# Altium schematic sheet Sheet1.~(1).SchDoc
size A4
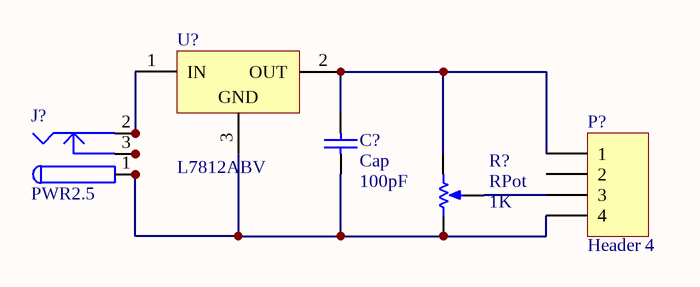
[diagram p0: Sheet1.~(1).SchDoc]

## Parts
C?  Cap  value 100pF  [RAD-0.3]
J?  PWR2.5  [KLD-0202]
P?  Header 4  [HDR1X4]
R?  RPot  value 1K  [VR5]
U?  L7812ABV  [TO220ABN]

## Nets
NetC?_1: C?.1 J?.1 J?.1A J?.1B P?.4 R?.1(TOP) U?.3(GND)
NetC?_2: C?.2 P?.1 R?.2(BOT) U?.2(OUT)
NetJ?_2: J?.2 J?.2A J?.2B U?.1(IN)
NetJ?_3: J?.3 J?.3A J?.3B
NetP?_3: P?.3 R?.3(TAP)

Not connected (* = marked no-connect by the designer): P? 2

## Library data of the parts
C? = Cap: Capacitor
J? = PWR2.5: Low Voltage Power Supply Connector
P? = Header 4: Header, 4-Pin
R? = RPot: Potentiometer; Sim Note: Enter the Resistance value and the set point into parameter fields.; Set Position: 0.5
U? = L7812ABV: Precision 1A Regulator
